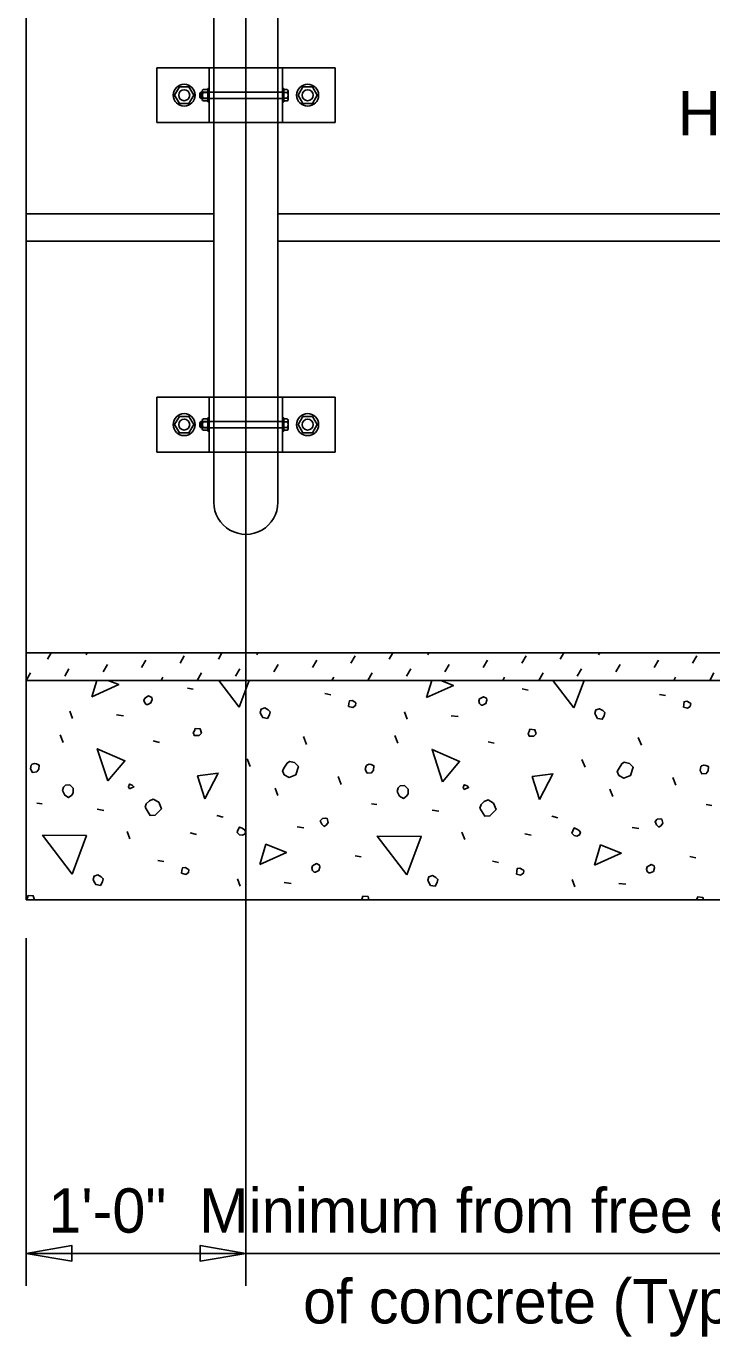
# Model space of a CAD drawing. Extents: x 0.2 to 40.8, y 0.5 to 25.7.
# Drawn here: x 3.62 to 6.74, y 11.11 to 17.08 of the extents above; entities that cross this region are included whole.
import ezdxf

# ---------------------------------------------------------------- set-up
doc = ezdxf.new("R2010")
doc.units = 0
for name, color, linetype in [('CL_Major', 7, 'Continuous'), ('Dimension', 7, 'Continuous'), ('Miscellaneous', 7, 'Continuous'), ('SteelMisc', 7, 'Continuous'), ('SteelMisc_h', 7, 'Continuous'), ('SupstrConc', 7, 'Continuous'), ('TextStructures', 7, 'Continuous')]:
    doc.layers.add(name, color=color, linetype=linetype)

msp = doc.modelspace()

# ---------------------------------------------------------------- linework, layer by layer
at = {"layer": 'CL_Major'}
msp.add_line((4.615, 25.5927), (4.615, 11.342), dxfattribs=at)
at = {"layer": 'Dimension'}
for p, q in [((3.615, 12.9261), (3.615, 11.342)), ((3.6151, 11.4901), (8.3895, 11.4901))]:
    msp.add_line(p, q, dxfattribs=at)
for points in [[(3.6151, 11.4901), (3.8233, 11.4549), (3.8233, 11.5254)], [(4.6151, 11.4902), (4.4068, 11.5255), (4.4068, 11.4549)]]:
    msp.add_lwpolyline(points, close=True, dxfattribs=at)
at = {"layer": 'Miscellaneous'}
for p, q in [((4.4075, 16.7575), (4.4075, 16.7696)), ((4.4132, 16.7575), (4.4132, 16.7696)), ((4.4075, 15.2575), (4.4075, 15.2696)), ((4.4132, 15.2575), (4.4132, 15.2696)), ((3.7123, 14.1967), (3.7283, 14.2245)), ((3.8873, 14.2162), (3.8921, 14.2245)), ((4.3151, 14.1773), (4.3345, 14.2109)), ((4.4901, 14.1967), (4.5062, 14.2245)), ((4.6651, 14.2162), (4.6699, 14.2245)), ((5.0929, 14.1773), (5.1123, 14.2109)), ((5.2679, 14.1967), (5.284, 14.2245)), ((5.4429, 14.2162), (5.4477, 14.2245)), ((5.8707, 14.1773), (5.8902, 14.2109)), ((6.0457, 14.1967), (6.0618, 14.2245)), ((6.2207, 14.2162), (6.2255, 14.2245)), ((6.6485, 14.1773), (6.668, 14.2109)), ((3.7901, 14.119), (3.8095, 14.1526)), ((3.9651, 14.1384), (3.9845, 14.172)), ((4.1401, 14.1579), (4.1595, 14.1914)), ((4.5679, 14.119), (4.5873, 14.1526)), ((4.7429, 14.1384), (4.7623, 14.172)), ((4.9179, 14.1579), (4.9373, 14.1914)), ((5.3457, 14.119), (5.3651, 14.1526)), ((5.5207, 14.1384), (5.5401, 14.172)), ((5.6957, 14.1579), (5.7152, 14.1914)), ((6.1235, 14.119), (6.143, 14.1526)), ((6.2985, 14.1384), (6.318, 14.172)), ((6.4735, 14.1579), (6.493, 14.1914)), ((3.615, 14.0995), (3.6345, 14.1331)), ((4.2291, 14.0995), (4.2373, 14.1137)), ((4.3929, 14.0995), (4.4123, 14.1331)), ((5.0069, 14.0995), (5.0151, 14.1137)), ((5.1707, 14.0995), (5.1901, 14.1331)), ((5.7847, 14.0995), (5.7929, 14.1137)), ((5.9485, 14.0995), (5.9679, 14.1331)), ((6.5626, 14.0995), (6.5708, 14.1137)), ((6.7263, 14.0995), (6.7458, 14.1331)), ((4.3489, 14.0642), (4.3754, 14.0589)), ((4.9746, 14.0394), (5.0012, 14.0341)), ((5.8727, 14.0606), (5.8992, 14.0553)), ((6.4985, 14.0359), (6.525, 14.0306)), ((3.8256, 13.9263), (3.8132, 13.9599)), ((4.0254, 13.9422), (4.0572, 13.9387)), ((5.3494, 13.9227), (5.337, 13.9563)), ((5.5492, 13.9387), (5.581, 13.9351)), ((3.7832, 13.8167), (3.769, 13.852)), ((5.307, 13.8131), (5.2928, 13.8485)), ((4.1933, 13.8237), (4.2216, 13.8167)), ((4.8916, 13.8078), (4.8774, 13.8432)), ((5.7171, 13.8202), (5.7454, 13.8131)), ((6.4154, 13.8043), (6.4012, 13.8397)), ((4.6352, 13.7071), (4.6211, 13.7424)), ((6.1591, 13.7035), (6.1449, 13.7389)), ((4.7607, 13.5745), (4.7484, 13.6081)), ((5.0489, 13.6258), (5.0348, 13.6611)), ((6.5727, 13.6222), (6.5586, 13.6576)), ((6.2846, 13.571), (6.2722, 13.6045)), ((3.663, 13.5409), (3.6877, 13.5374)), ((3.9387, 13.5126), (3.9688, 13.5073)), ((5.1868, 13.5374), (5.2115, 13.5338)), ((5.4626, 13.5091), (5.4926, 13.5038)), ((6.7106, 13.5338), (6.7353, 13.5303)), ((4.4832, 13.4843), (4.5115, 13.4773)), ((4.8491, 13.4331), (4.8792, 13.4278)), ((6.007, 13.4808), (6.0353, 13.4737)), ((6.373, 13.4295), (6.403, 13.4242)), ((4.0872, 13.3783), (4.0749, 13.4119)), ((4.3612, 13.4048), (4.3895, 13.3977)), ((5.611, 13.3747), (5.5987, 13.4083)), ((5.885, 13.4013), (5.9133, 13.3942)), ((3.615, 13.2988), (3.6152, 13.2987)), ((4.2145, 13.2793), (4.241, 13.274)), ((5.1125, 13.3005), (5.1391, 13.2952)), ((5.7383, 13.2757), (5.7648, 13.2704)), ((6.6363, 13.297), (6.6629, 13.2917)), ((4.5893, 13.1626), (4.5769, 13.1962)), ((6.1131, 13.1591), (6.1007, 13.1927)), ((4.789, 13.1785), (4.8209, 13.175)), ((6.3128, 13.175), (6.3447, 13.1714))]:
    msp.add_line(p, q, dxfattribs=at)
for points in [[(3.914, 14.0253), (3.9368, 14.0995)], [(3.9869, 14.0995), (4.036, 14.0801), (3.914, 14.0253)], [(4.584, 13.9775), (4.4913, 14.0995)], [(4.6296, 14.0995), (4.584, 13.9775)], [(5.4378, 14.0217), (5.4617, 14.0995)], [(5.5018, 14.0995), (5.5598, 14.0765), (5.4378, 14.0217)], [(6.1078, 13.974), (6.0124, 14.0995)], [(6.1547, 14.0995), (6.1078, 13.974)], [(4.1615, 13.9899), (4.1685, 13.9899), (4.1827, 13.997), (4.188, 14.0129), (4.1862, 14.0217), (4.1721, 14.0288), (4.1544, 14.0182), (4.1509, 14.0076), (4.1544, 13.997), (4.1615, 13.9899)], [(4.683, 13.9457), (4.6918, 13.9298), (4.713, 13.9263), (4.7219, 13.9422), (4.7254, 13.9563), (4.7166, 13.9652), (4.7006, 13.974), (4.6847, 13.9687), (4.6794, 13.9528), (4.683, 13.9457)], [(5.0825, 13.9811), (5.1019, 13.9758), (5.1143, 13.9846), (5.1161, 13.997), (5.1125, 14.0005), (5.0984, 14.0076), (5.086, 14.0058), (5.0843, 13.9935), (5.0825, 13.9811)], [(5.6853, 13.9864), (5.6924, 13.9864), (5.7065, 13.9935), (5.7118, 14.0094), (5.71, 14.0182), (5.6959, 14.0253), (5.6782, 14.0147), (5.6747, 14.0041), (5.6782, 13.9935), (5.6853, 13.9864)], [(6.2068, 13.9422), (6.2156, 13.9263), (6.2368, 13.9227), (6.2457, 13.9387), (6.2492, 13.9528), (6.2404, 13.9616), (6.2245, 13.9705), (6.2086, 13.9652), (6.2032, 13.9493), (6.2068, 13.9422)], [(6.6063, 13.9775), (6.6257, 13.9722), (6.6381, 13.9811), (6.6399, 13.9935), (6.6363, 13.997), (6.6222, 14.0041), (6.6098, 14.0023), (6.6081, 13.9899), (6.6063, 13.9775)], [(4.3807, 13.8485), (4.4019, 13.8485), (4.4125, 13.8591), (4.4072, 13.8786), (4.3842, 13.8803), (4.3807, 13.8697), (4.3754, 13.8609), (4.3807, 13.8485), (4.3771, 13.852)], [(5.9045, 13.845), (5.9257, 13.845), (5.9363, 13.8556), (5.931, 13.875), (5.908, 13.8768), (5.9045, 13.8662), (5.8992, 13.8573), (5.9045, 13.845), (5.901, 13.8485)], [(3.9865, 13.6417), (3.9387, 13.7884), (4.0642, 13.7336), (3.9865, 13.6417)], [(4.789, 13.67), (4.812, 13.6576), (4.8421, 13.67), (4.8544, 13.7071), (4.8368, 13.7248), (4.8138, 13.7301), (4.8032, 13.723), (4.7908, 13.7035), (4.782, 13.6876), (4.789, 13.67)], [(5.5103, 13.6381), (5.4626, 13.7849), (5.5881, 13.7301), (5.5103, 13.6381)], [(3.6347, 13.6965), (3.6435, 13.6806), (3.663, 13.6823), (3.6718, 13.6947), (3.6736, 13.7141), (3.6612, 13.7195), (3.6524, 13.7212), (3.6418, 13.7177), (3.6382, 13.7141), (3.6347, 13.6965)], [(4.4284, 13.5604), (4.3948, 13.6647), (4.4885, 13.677), (4.4284, 13.5604)], [(5.1585, 13.6929), (5.1673, 13.677), (5.1868, 13.6788), (5.1956, 13.6912), (5.1974, 13.7106), (5.185, 13.7159), (5.1762, 13.7177), (5.1656, 13.7141), (5.162, 13.7106), (5.1585, 13.6929)], [(5.9522, 13.5568), (5.9186, 13.6611), (6.0123, 13.6735), (5.9522, 13.5568)], [(6.3128, 13.6664), (6.3358, 13.654), (6.3659, 13.6664), (6.3783, 13.7035), (6.3606, 13.7212), (6.3376, 13.7265), (6.327, 13.7195), (6.3146, 13.7), (6.3058, 13.6841), (6.3128, 13.6664)], [(6.6823, 13.6894), (6.6912, 13.6735), (6.7106, 13.6753), (6.7194, 13.6876), (6.7212, 13.7071), (6.7088, 13.7124), (6.7, 13.7141), (6.6894, 13.7106), (6.6858, 13.7071), (6.6823, 13.6894)], [(3.7796, 13.5975), (3.7902, 13.5763), (3.8079, 13.5657), (3.8221, 13.5763), (3.8291, 13.5869), (3.8291, 13.6081), (3.8132, 13.624), (3.7938, 13.6222), (3.7849, 13.6134), (3.7796, 13.5975)], [(4.0855, 13.6063), (4.1049, 13.6152), (4.0978, 13.6222), (4.0855, 13.6275), (4.0802, 13.6152), (4.0855, 13.6063)], [(5.3035, 13.5939), (5.3141, 13.5727), (5.3317, 13.5621), (5.3459, 13.5727), (5.353, 13.5833), (5.353, 13.6045), (5.337, 13.6205), (5.3176, 13.6187), (5.3088, 13.6098), (5.3035, 13.5939)], [(5.6093, 13.6028), (5.6287, 13.6116), (5.6217, 13.6187), (5.6093, 13.624), (5.604, 13.6116), (5.6093, 13.6028)], [(4.1562, 13.5215), (4.1792, 13.4843), (4.2021, 13.4861), (4.211, 13.4949), (4.2304, 13.5144), (4.218, 13.5444), (4.1933, 13.5586), (4.1756, 13.5515), (4.1615, 13.5374), (4.1562, 13.5215)], [(5.68, 13.5179), (5.703, 13.4808), (5.7259, 13.4826), (5.7348, 13.4914), (5.7542, 13.5109), (5.7419, 13.5409), (5.7171, 13.555), (5.6994, 13.548), (5.6853, 13.5338), (5.68, 13.5179)], [(4.5857, 13.3959), (4.5981, 13.3942), (4.6105, 13.3995), (4.614, 13.4101), (4.6087, 13.4189), (4.5981, 13.426), (4.5857, 13.4313), (4.5787, 13.4172), (4.5751, 13.4066), (4.5857, 13.3959)], [(4.9605, 13.4454), (4.9711, 13.4348), (4.9817, 13.4419), (4.9888, 13.4525), (4.9853, 13.4702), (4.9764, 13.472), (4.964, 13.4702), (4.9534, 13.4596), (4.9605, 13.4454)], [(6.4843, 13.4419), (6.4949, 13.4313), (6.5055, 13.4384), (6.5126, 13.449), (6.5091, 13.4667), (6.5002, 13.4684), (6.4879, 13.4667), (6.4773, 13.4561), (6.4843, 13.4419)], [(3.8238, 13.2174), (3.6895, 13.3942), (3.8892, 13.3924), (3.8238, 13.2174)], [(5.3476, 13.2139), (5.2133, 13.3906), (5.4131, 13.3889), (5.3476, 13.2139)], [(6.1096, 13.3924), (6.1219, 13.3906), (6.1343, 13.3959), (6.1378, 13.4066), (6.1325, 13.4154), (6.1219, 13.4225), (6.1096, 13.4278), (6.1025, 13.4136), (6.0989, 13.403), (6.1096, 13.3924)], [(4.6777, 13.2616), (4.7059, 13.3535), (4.7996, 13.3164), (4.6777, 13.2616)], [(6.2015, 13.2581), (6.2298, 13.35), (6.3235, 13.3129), (6.2015, 13.2581)], [(4.9252, 13.2262), (4.9322, 13.2262), (4.9464, 13.2333), (4.9517, 13.2492), (4.9499, 13.2581), (4.9358, 13.2651), (4.9181, 13.2545), (4.9145, 13.2439), (4.9181, 13.2333), (4.9252, 13.2262)], [(6.449, 13.2227), (6.456, 13.2227), (6.4702, 13.2298), (6.4755, 13.2457), (6.4737, 13.2545), (6.4596, 13.2616), (6.4419, 13.251), (6.4384, 13.2404), (6.4419, 13.2298), (6.449, 13.2227)], [(3.9228, 13.1856), (3.9317, 13.1697), (3.9529, 13.1661), (3.9617, 13.1821), (3.9653, 13.1962), (3.9564, 13.205), (3.9405, 13.2139), (3.9246, 13.2086), (3.9193, 13.1927), (3.9228, 13.1856)], [(4.3223, 13.2209), (4.3418, 13.2156), (4.3542, 13.2245), (4.3559, 13.2369), (4.3524, 13.2404), (4.3383, 13.2475), (4.3259, 13.2457), (4.3241, 13.2333), (4.3223, 13.2209)], [(5.4466, 13.1821), (5.4555, 13.1661), (5.4767, 13.1626), (5.4855, 13.1785), (5.4891, 13.1927), (5.4802, 13.2015), (5.4643, 13.2103), (5.4484, 13.205), (5.4431, 13.1891), (5.4466, 13.1821)], [(5.8462, 13.2174), (5.8656, 13.2121), (5.878, 13.2209), (5.8797, 13.2333), (5.8762, 13.2369), (5.8621, 13.2439), (5.8497, 13.2422), (5.8479, 13.2298), (5.8462, 13.2174)], [(3.6522, 13.0995), (3.6471, 13.1184), (3.6241, 13.1202), (3.6205, 13.1096), (3.6152, 13.1007), (3.6158, 13.0995)], [(5.1751, 13.0995), (5.1709, 13.1149), (5.1479, 13.1166), (5.1444, 13.106), (5.1404, 13.0995)], [(6.6979, 13.0995), (6.6947, 13.1113), (6.6717, 13.1131), (6.6682, 13.1025), (6.6664, 13.0995)]]:
    msp.add_lwpolyline(points, dxfattribs=at)
at = {"layer": 'SteelMisc'}
for p, q in [((4.4692, 16.8894), (4.4692, 17.3653)), ((4.7609, 16.8894), (4.7609, 17.3653)), ((4.2091, 16.8894), (5.021, 16.8894)), ((4.2091, 16.6394), (4.2091, 16.8894)), ((4.4484, 16.8894), (4.4484, 16.6394)), ((4.7817, 16.8894), (4.7817, 16.6394)), ((5.021, 16.8894), (5.021, 16.6394)), ((4.4047, 16.7724), (4.4103, 16.7789)), ((4.4047, 16.7547), (4.4047, 16.7724)), ((4.4103, 16.7789), (4.4168, 16.7789)), ((4.4103, 16.749), (4.4103, 16.7789)), ((4.4168, 16.7823), (4.4168, 16.7465)), ((4.4215, 16.7774), (4.4418, 16.7774)), ((4.4217, 16.7904), (4.4418, 16.7904)), ((4.4418, 16.7947), (4.4418, 16.734)), ((4.4418, 16.7947), (4.4484, 16.7947)), ((4.4418, 16.7904), (4.4418, 16.7384)), ((4.788, 16.7947), (4.782, 16.7947)), ((4.788, 16.7947), (4.788, 16.734)), ((4.8027, 16.7903), (4.788, 16.7903)), ((4.8028, 16.7773), (4.788, 16.7773)), ((4.8078, 16.745), (4.8078, 16.7838)), ((4.4047, 16.7547), (4.4103, 16.749)), ((4.4103, 16.749), (4.4168, 16.749)), ((4.4215, 16.7514), (4.4418, 16.7514)), ((4.4218, 16.7384), (4.4418, 16.7384)), ((4.4418, 16.734), (4.4484, 16.734)), ((4.788, 16.734), (4.782, 16.734)), ((4.8028, 16.7514), (4.788, 16.7514)), ((4.8027, 16.7384), (4.788, 16.7384)), ((5.021, 16.6394), (4.2091, 16.6394)), ((4.4692, 16.6394), (4.4692, 15.3894)), ((4.7609, 16.6394), (4.7609, 15.3894)), ((4.2091, 15.3894), (5.021, 15.3894)), ((4.2091, 15.1394), (4.2091, 15.3894)), ((4.4484, 15.3894), (4.4484, 15.1394)), ((4.7817, 15.3894), (4.7817, 15.1394)), ((5.021, 15.3894), (5.021, 15.1394)), ((4.4168, 15.2823), (4.4168, 15.2465)), ((4.4217, 15.2904), (4.4418, 15.2904)), ((4.4418, 15.2947), (4.4418, 15.234)), ((4.4418, 15.2947), (4.4484, 15.2947)), ((4.4418, 15.2904), (4.4418, 15.2384)), ((4.788, 15.2947), (4.782, 15.2947)), ((4.788, 15.2947), (4.788, 15.234)), ((4.8027, 15.2903), (4.788, 15.2903)), ((4.8078, 15.245), (4.8078, 15.2838)), ((4.4047, 15.2724), (4.4103, 15.2789)), ((4.4047, 15.2547), (4.4047, 15.2724)), ((4.4047, 15.2547), (4.4103, 15.249)), ((4.4103, 15.2789), (4.4168, 15.2789)), ((4.4103, 15.249), (4.4103, 15.2789)), ((4.4103, 15.249), (4.4168, 15.249)), ((4.4215, 15.2774), (4.4418, 15.2774)), ((4.4215, 15.2514), (4.4418, 15.2514)), ((4.4218, 15.2384), (4.4418, 15.2384)), ((4.4418, 15.234), (4.4484, 15.234)), ((4.788, 15.234), (4.782, 15.234)), ((4.8028, 15.2773), (4.788, 15.2773)), ((4.8028, 15.2514), (4.788, 15.2514)), ((4.8027, 15.2384), (4.788, 15.2384)), ((5.021, 15.1394), (4.2091, 15.1394)), ((4.4691, 15.1394), (4.4691, 14.9102)), ((4.7608, 14.9102), (4.7608, 15.1394))]:
    msp.add_line(p, q, dxfattribs=at)
for points in [[(4.3124, 16.8019), (4.3557, 16.8019), (4.3774, 16.7644), (4.3557, 16.7269), (4.3124, 16.7269), (4.2907, 16.7644)], [(4.8744, 16.8019), (4.9177, 16.8019), (4.9394, 16.7644), (4.9177, 16.7269), (4.8744, 16.7269), (4.8527, 16.7644)], [(4.3124, 15.3019), (4.3557, 15.3019), (4.3774, 15.2644), (4.3557, 15.2269), (4.3124, 15.2269), (4.2907, 15.2644)], [(4.8744, 15.3019), (4.9177, 15.3019), (4.9394, 15.2644), (4.9177, 15.2269), (4.8744, 15.2269), (4.8527, 15.2644)]]:
    msp.add_lwpolyline(points, close=True, dxfattribs=at)
for centre, radius in [((4.3341, 16.7644), 0.05), ((4.3341, 16.7644), 0.025), ((4.896, 16.7644), 0.05), ((4.896, 16.7644), 0.025), ((4.3341, 15.2644), 0.05), ((4.3341, 15.2644), 0.025), ((4.896, 15.2644), 0.05), ((4.896, 15.2644), 0.025)]:
    msp.add_circle(centre, radius, dxfattribs=at)
for centre, radius, start, end in [((4.4234, 16.7838), 0.00674, 104.48908, 254.18889), ((4.4363, 16.7644), 0.0196, 138.62797, 221.37203), ((4.801, 16.7838), 0.00673, 285.7823, 75.54039), ((4.7881, 16.7644), 0.0196, 318.62797, 41.37203), ((4.4234, 16.7449), 0.00673, 105.7823, 255.54039), ((4.801, 16.7449), 0.00674, 284.48908, 74.18889), ((4.4234, 15.2838), 0.00674, 104.48908, 254.18889), ((4.801, 15.2838), 0.00673, 285.7823, 75.54039), ((4.4363, 15.2644), 0.0196, 138.62797, 221.37203), ((4.4234, 15.2449), 0.00673, 105.7823, 255.54039), ((4.801, 15.2449), 0.00674, 284.48908, 74.18889), ((4.7881, 15.2644), 0.0196, 318.62797, 41.37203)]:
    msp.add_arc(centre, radius, start, end, dxfattribs=at)
msp.add_ellipse((4.615, 14.9102), major_axis=(0, 0.1458), ratio=0.999499, start_param=1.570796, end_param=4.712389, dxfattribs=at)
at = {"layer": 'SteelMisc_h'}
for p, q in [((4.4692, 16.8894), (4.4692, 16.6394)), ((4.7609, 16.8894), (4.7609, 16.6394)), ((4.7817, 16.7789), (4.4168, 16.7789)), ((4.4168, 16.749), (4.7817, 16.749)), ((4.4692, 15.3894), (4.4692, 15.1394)), ((4.7609, 15.3894), (4.7609, 15.1394)), ((4.7817, 15.2789), (4.4168, 15.2789)), ((4.4168, 15.249), (4.7817, 15.249))]:
    msp.add_line(p, q, dxfattribs=at)
at = {"layer": 'SupstrConc'}
for p, q in [((3.615, 17.2245), (3.615, 13.0995)), ((3.615, 16.2245), (4.4692, 16.2245)), ((4.7609, 16.2245), (14.4692, 16.2245)), ((3.6151, 16.0995), (4.4692, 16.0995)), ((4.7609, 16.0995), (14.4692, 16.0995)), ((3.615, 14.2245), (16.002, 14.2245)), ((16.002, 14.0995), (3.615, 14.0995)), ((16.002, 13.0995), (3.615, 13.0995))]:
    msp.add_line(p, q, dxfattribs=at)

# ---------------------------------------------------------------- texts
at = {"layer": 'TextStructures'}
for s, p in [('Hog Rings @ 2\'-0" Centers', (6.5816, 16.5823)), ('1\'-0"  Minimum from free end ', (3.7161, 11.5845)), ('of concrete (Typ.)', (4.8754, 11.171))]:
    msp.add_text(s, height=0.2016, dxfattribs=at).set_placement(p)

doc.saveas('drawing.dxf')
